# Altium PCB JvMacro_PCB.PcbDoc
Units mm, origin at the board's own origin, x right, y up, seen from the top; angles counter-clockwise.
Board outline 68.58 x 53.34 mm, 2 copper layers (Top Layer, Bottom Layer); 16 components, 30 nets, 104 pads, 8 vias.
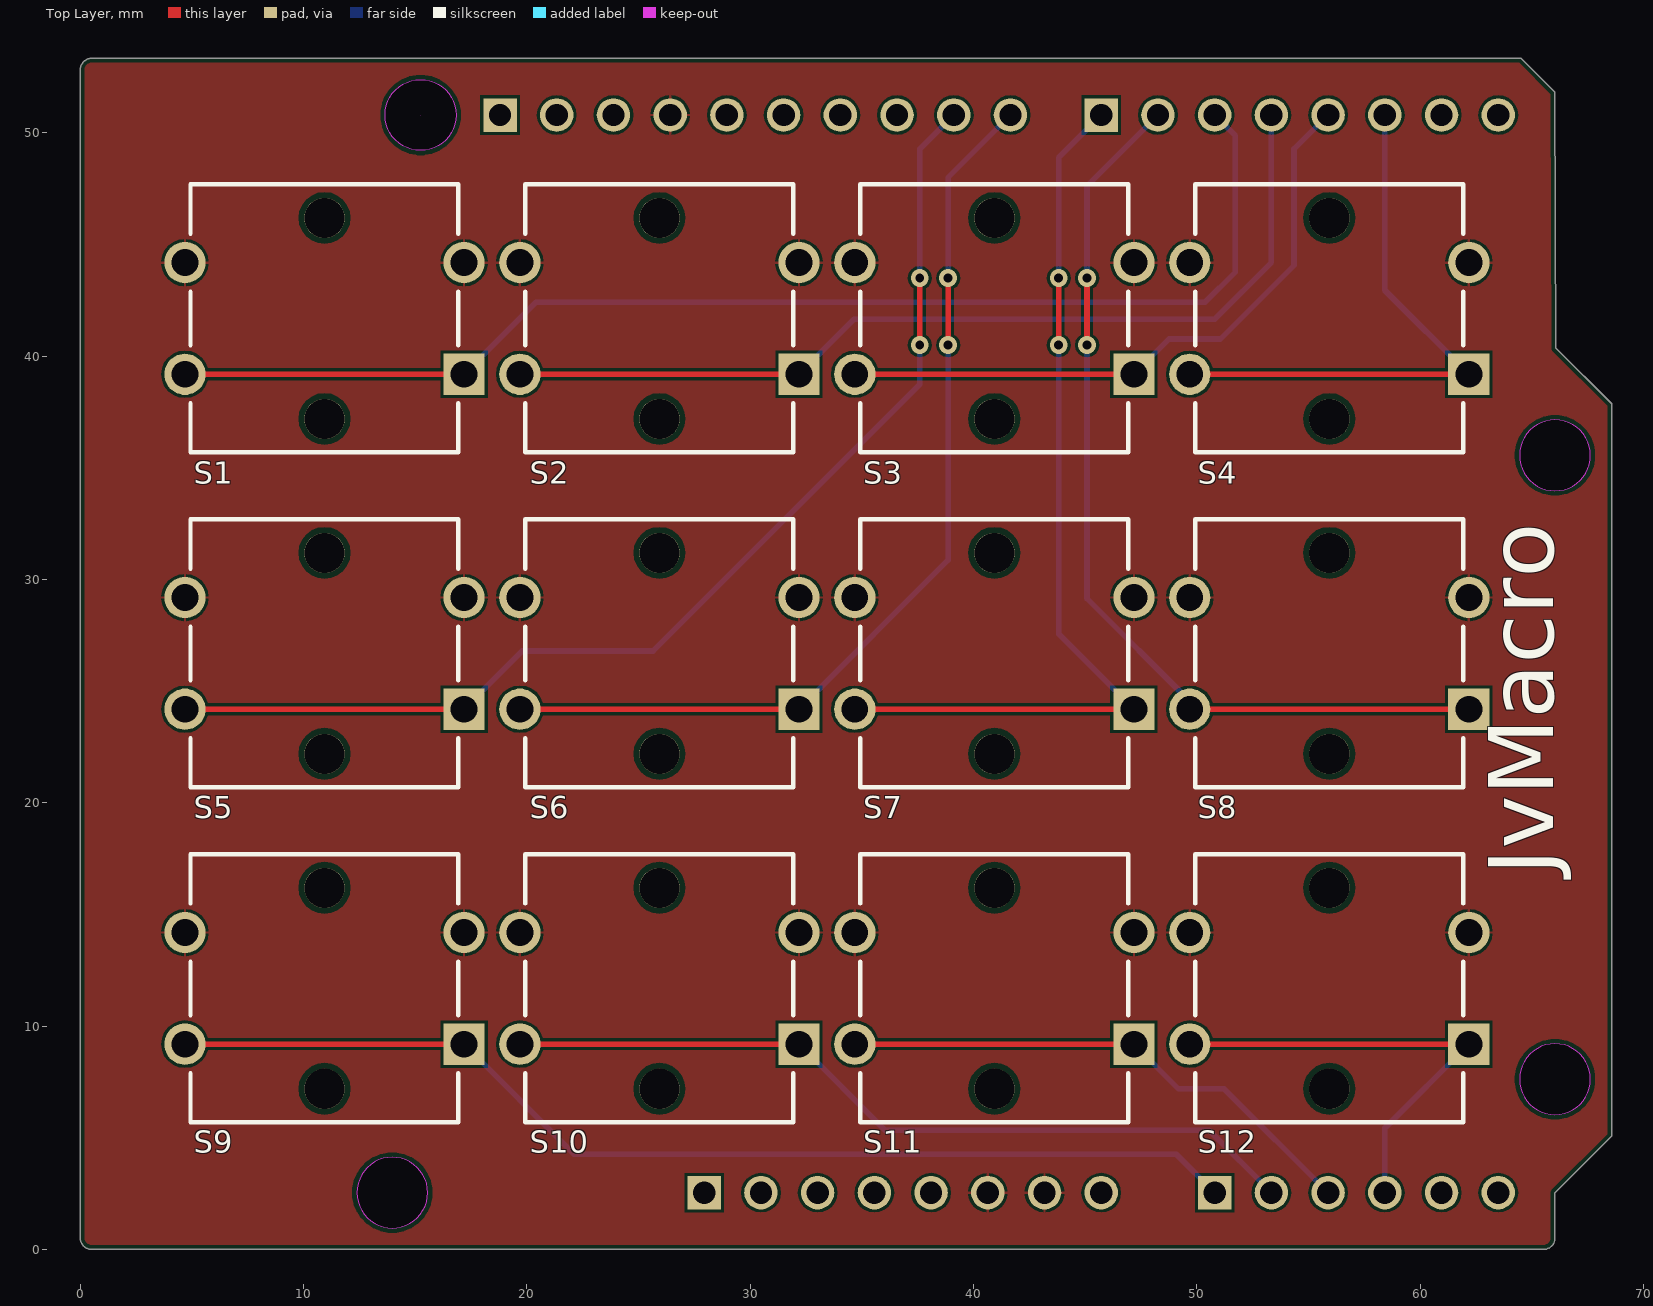
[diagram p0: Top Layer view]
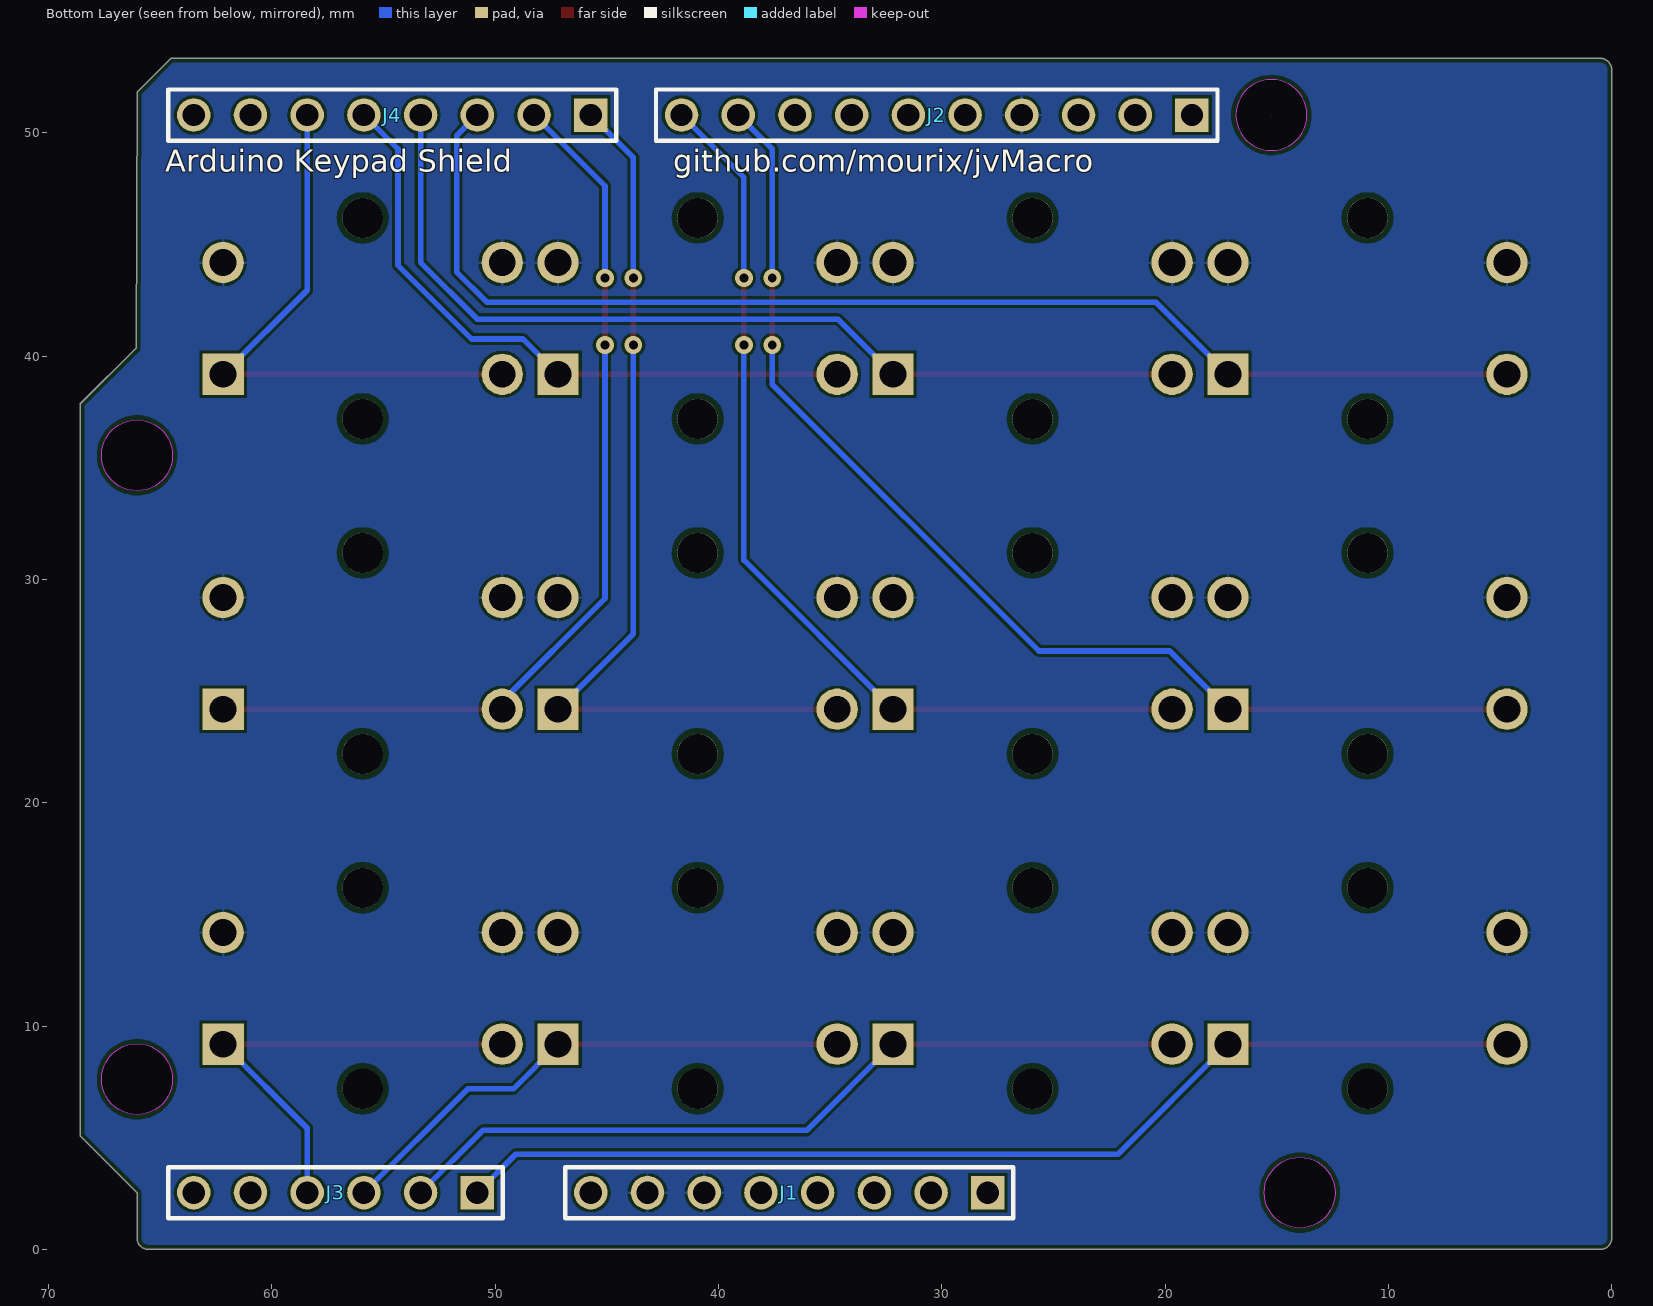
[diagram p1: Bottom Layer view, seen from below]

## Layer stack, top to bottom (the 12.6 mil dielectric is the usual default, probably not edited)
Top Solder: solder mask 0.0102, Solder Resist, Dk 3.5
Top Layer: signal copper 0.0356
Dielectric 1: dielectric 0.32, FR-4, Dk 4.8
Bottom Layer: signal copper 0.0356
Bottom Solder: solder mask 0.0102, Solder Resist, Dk 3.5

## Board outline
0,0.508 0,52.832 cw(c0.508,52.832) 0.508,53.34 64.516,53.34 66.04,51.816 66.07,40.386 66.07,40.376 68.58,37.866 68.58,5.08 66.04,2.54 66.04,0.508 cw(c65.532,0.508) 65.532,0 0.508,0 cw(c0.508,0.508)
cut-out: 15.24,49.212 cw(c15.24,50.8) 13.652,50.8 cw(c15.24,50.8) 15.24,52.387 cw(c15.24,50.8) 16.828,50.8 cw(c15.24,50.8)
cut-out: 64.453,7.62 ccw(c66.04,7.62) 66.04,6.032 ccw(c66.04,7.62) 67.627,7.62 ccw(c66.04,7.62) 66.04,9.207 ccw(c66.04,7.62)
cut-out: 64.453,35.56 ccw(c66.04,35.56) 66.04,33.972 ccw(c66.04,35.56) 67.627,35.56 ccw(c66.04,35.56) 66.04,37.148 ccw(c66.04,35.56)
cut-out: 12.383,2.54 ccw(c13.97,2.54) 13.97,0.953 ccw(c13.97,2.54) 15.557,2.54 ccw(c13.97,2.54) 13.97,4.127 ccw(c13.97,2.54)
cut-out: 15.24,50.8

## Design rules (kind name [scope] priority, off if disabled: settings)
BoardOutlineClearance [All] p1: gap=0.2 ignorepadtopadclearanceinfootprint=FALSE
Clearance [All] p1: gap=0.127 ignorepadtopadclearanceinfootprint=FALSE except(0.25: Arc-Hole Track-Hole SMDPad-Hole THPad-Hole Via-Hole Fill-Hole Poly-Hole Region-Hole Text-Hole)
ComponentClearance [All] p1: gap=0.127 collisioncheckmode=3 verticalgap=0.127 showdistances=TRUE
DiffPairsRouting [All] p1: maxlimit=0.254 minlimit=0.127 mostfreqgap=0.127 toplayer_minwidth=0.127 toplayer_maxwidth=25.4 toplayer_prefwidth=0.127 bottomlayer_minwidth=0.127 bottomlayer_maxwidth=25.4 bottomlayer_prefwidth=0.127 maxuncoupledlength=12.7
Height [All] p1: minheight=0 maxheight=1816.048 prefheight=12.7
HoleSize [All] p1: absolutevalues=TRUE maxlimit=6.3 minlimit=0.3 maxpercent=80.000 minpercent=20.000
HoleToHoleClearance [All] p1: gap=0.25 allowstackedmicrovias=FALSE
MinimumAnnularRing [All] p1: minimumring=0.076
MinimumSolderMaskSliver [All] p1: minsoldermaskwidth=0
PlaneClearance [All] p1: clearance=0.127
PlaneConnect PlaneConnectPowerPads [InPadClass('PowerPads')] p1: planeconnectstyle=Direct reliefexpansion=0.508 reliefentries=4 reliefconductorwidth=0.254 reliefairgap=0.254
PlaneConnect [All] p2: pad.planeconnectstyle=Relief pad.reliefexpansion=0.3 pad.reliefentries=4 pad.reliefconductorwidth=0.127 pad.reliefairgap=0.127 via.planeconnectstyle=Direct via.reliefexpansion=0.3 via.reliefentries=4 via.reliefconductorwidth=0.127 via.reliefairgap=0.127
PolygonConnect PolygonConnectPowerPads [All vs (InPadClass('PowerPads'))] p1: connectstyle=Direct reliefconductorwidth=0.254 reliefentries=4 polygonreliefangle="90 Angle" airgapwidth=0.254
PolygonConnect [All] p2: thpad.connectstyle=Relief thpad.reliefconductorwidth=0.127 thpad.reliefentries=4 thpad.polygonreliefangle="90 Angle" thpad.airgapwidth=0.127 smdpad.connectstyle=Relief smdpad.reliefconductorwidth=0.127 smdpad.reliefentries=4 smdpad.polygonreliefangle="90 Angle" smdpad.airgapwidth=0.127 via.connectstyle=Direct via.reliefconductorwidth=0.127 via.reliefentries=4 via.polygonreliefangle="90 Angle" via.airgapwidth=0.127
RoutingVias [All] p1: holewidth=0.3 width=0.6 viastyle="Through Hole" minholewidth=0.3 minwidth=0.6 maxholewidth=0.6 maxwidth=6.6
SilkToSilkClearance [All] p1: silktosilkclearance=0
SilkToSolderMaskClearance [IsPad] p1: minsilkscreentomaskgap=0.127 clearancetoexposedcopper=TRUE
SolderMaskExpansion [All] p1: expansion=0.075
Width [All] p1: maxlimit=25.4 minlimit=0.127 preferedwidth=0.127 minimp=50.000000 maximp=50.000000 favimp=50.000000
20 further rules are at their usual default settings.

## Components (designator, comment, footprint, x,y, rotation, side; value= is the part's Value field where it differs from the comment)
J1 "Header 8" HDR1X8 27.94,2.54 r0 bottom locked
J2 "Header 10" HDR1X10 18.796,50.8 r0 bottom locked
J3 "Header 6" HDR1X6 50.8,2.54 r0 bottom locked
J4 "Header 8" HDR1X8 45.72,50.8 r0 bottom locked
S1 "B3F" Omron_B3F-4055 10.935,41.69 r0 top
S2 "B3F" Omron_B3F-4055 25.935,41.69 r0 top
S3 "B3F" Omron_B3F-4055 40.935,41.69 r0 top
S4 "B3F" Omron_B3F-4055 55.935,41.69 r0 top
S5 "B3F" Omron_B3F-4055 10.935,26.69 r0 top
S6 "B3F" Omron_B3F-4055 25.935,26.69 r0 top
S7 "B3F" Omron_B3F-4055 40.935,26.69 r0 top
S8 "B3F" Omron_B3F-4055 55.935,26.69 r0 top
S9 "B3F" Omron_B3F-4055 10.935,11.69 r0 top
S10 "B3F" Omron_B3F-4055 25.935,11.69 r0 top
S11 "B3F" Omron_B3F-4055 40.935,11.69 r0 top
S12 "B3F" Omron_B3F-4055 55.935,11.69 r0 top

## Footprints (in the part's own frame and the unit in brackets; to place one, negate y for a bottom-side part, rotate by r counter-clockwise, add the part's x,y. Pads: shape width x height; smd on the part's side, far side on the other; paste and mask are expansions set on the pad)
HDR1X6 [mm] "Connector; Header; 6 Position; Vertical"
  rect 1.5x1.5 hole 1: 1(0,0)
  round 1.5 hole 1: 2(2.54,0) 3(5.08,0) 4(7.62,0) 5(10.16,0) 6(12.7,0)
  silkscreen extent -1.14,-1.14 13.84,1.14, body extent -1.27,-1.27 13.97,1.27, height 6.54
HDR1X8 [mm] "Connector; Header; 8 Position; Vertical"
  rect 1.5x1.5 hole 1: 1(0,0)
  round 1.5 hole 1: 2(2.54,0) 3(5.08,0) 4(7.62,0) 5(10.16,0) 6(12.7,0) 7(15.24,0) 8(17.78,0)
  silkscreen extent -1.14,-1.14 18.92,1.14, body extent -1.27,-1.27 19.05,1.27, height 6.54
HDR1X10 [mm] "Connector; Header; 10 Position; Vertical"
  rect 1.5x1.5 hole 1: 1(0,0)
  round 1.5 hole 1: 2(2.54,0) 3(5.08,0) 4(7.62,0) 5(10.16,0) 6(12.7,0) 7(15.24,0) 8(17.78,0) 9(20.32,0) 10(22.86,0)
  silkscreen extent -1.14,-1.14 24,1.14, body extent -1.27,-1.27 24.13,1.27, height 6.54
Omron_B3F-4055 [mm]
  rect 1.85x1.85 hole 1.2 paste-1000 mask+0: 1(6.25,-2.5)
  round 1.85 hole 1.2 paste-1000 mask+0: 2(-6.25,-2.5) 3(6.25,2.5) 4(-6.25,2.5)
  round 1.8 hole 1.8 unplated paste-1000 mask+0: ""(0,-4.5) ""(0,4.5)
  silkscreen extent -6,-6 6,6, body extent -6.9,-6 6.9,6, height 10.5

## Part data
J1 J4: "2,54mm pitch header, 8 positions"
J2: "2,54mm pitch header, 10 positions"
J3: "2,54mm pitch header, 6 positions"
S1 S2 S3 S4 S5 S6 S7 S8 S9 S10 S11 S12: library part B3F-4055, "B3F pushbutton, 12x12mm, through hole"

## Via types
v1: diameter 0.8, hole 0.4, Top Layer to Bottom Layer, tented both sides, 8 vias

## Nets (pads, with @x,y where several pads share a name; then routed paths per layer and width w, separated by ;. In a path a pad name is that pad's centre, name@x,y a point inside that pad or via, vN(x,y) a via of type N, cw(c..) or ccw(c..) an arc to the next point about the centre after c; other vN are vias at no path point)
3.3V: J1.4
5V: J1.5
A0: J3.1 S9.1 S9.2 | length 48.9
  Top Layer w0.254: S9.2 S9.1
  Bottom Layer w0.254: S9.1 22.113,4.262 49.078,4.262 J3.1
A1: J3.2 S10.1 S10.2 | length 36.4
  Top Layer w0.254: S10.2 S10.1
  Bottom Layer w0.254: S10.1 36.041,5.334 50.546,5.334 J3.2
A2: J3.3 S11.1 S11.2 | length 23.9
  Top Layer w0.254: S11.2 S11.1
  Bottom Layer w0.254: S11.1 49.185,7.19 51.23,7.19 J3.3
A3: J3.4 S12.1 S12.2 | length 20.7
  Top Layer w0.254: S12.2 S12.1
  Bottom Layer w0.254: J3.4 58.42,5.425 S12.1
A4: J3.5
A5: J3.6
ARF: J2.3
D0: J4.8
D1: J4.7
D2: J4.6 S4.1 S4.2 | length 25.7
  Top Layer w0.254: S4.2 S4.1
  Bottom Layer w0.254: J4.6 58.42,42.955 S4.1
D3: J4.5 S3.1 S3.2 | length 29.1
  Top Layer w0.254: S3.2 S3.1
  Bottom Layer w0.254: S3.1 48.762,40.767 51.054,40.767 54.356,44.069 54.356,49.276 J4.5
D4: J4.4 S2.1 S2.2 | length 42.3
  Top Layer w0.254: S2.2 S2.1
  Bottom Layer w0.254: S2.1 34.651,41.656 50.8,41.656 53.34,44.196 J4.4
D5: J4.3 S1.1 S1.2 | length 56.4
  Top Layer w0.254: S1.2 S1.1
  Bottom Layer w0.254: S1.1 20.413,42.418 50.371,42.418 51.726,43.774 51.726,49.874 J4.3
D6: J4.2 S8.1 S8.2 | length 42.4
  Top Layer w0.254: v1@45.085,40.513 v1(45.085,43.5) ; S8.2 S8.1
  Bottom Layer w0.254: v1@45.085,40.513 v1(45.085,40.5) 45.085,29.149 49.685,24.549 S8.2 ; v1@45.085,43.434 v1(45.085,43.5) 45.085,47.625 J4.2
D7: J4.1 S7.1 S7.2 | length 41.4
  Top Layer w0.254: S7.2 S7.1 ; v1@43.815,40.513 v1(43.815,43.5)
  Bottom Layer w0.254: v1@43.815,40.513 v1(43.815,40.5) 43.815,27.56 S7.1 ; v1@43.815,43.434 v1(43.815,43.5) 43.815,48.895 J4.1
D8: J2.10 S6.1 S6.2 | length 43.2
  Top Layer w0.254: S6.2 S6.1 ; v1(38.862,40.5) v1(38.862,43.5)
  Bottom Layer w0.254: S6.1 38.862,30.867 v1(38.862,40.5) v1@38.862,40.64 ; v1(38.862,43.5) 38.862,48.006 J2.10
D9: J2.9 S5.1 S5.2 | length 51.8
  Top Layer w0.254: S5.2 S5.1 ; v1(37.592,40.5) v1(37.592,43.5)
  Bottom Layer w0.254: S5.1 19.792,26.797 25.653,26.797 37.592,38.736 v1(37.592,40.5) v1@37.592,40.64 ; v1(37.592,43.5) 37.592,49.276 J2.9
D10: J2.8
D11: J2.7
D12: J2.6
D13: J2.5
GND: J1.6 J1.7 J2.4 S1.3 S1.4 S2.3 S2.4 S3.3 S3.4 S4.3 S4.4 S5.3 S5.4 S6.3 S6.4 S7.3 S7.4 S8.3 S8.4 S9.3 S9.4 S10.3 S10.4 S11.3 S11.4 S12.3 S12.4
IOR: J1.2
NC: J1.1
RST: J1.3
SCL: J2.1
SDA: J2.2
Vin: J1.8
pads on no net: S1. S2. S3. S4. S5. S6. S7. S8. S9. S10. S11. S12.

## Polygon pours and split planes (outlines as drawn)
GND on Top Layer "GND_L01_P003" (solid, pour order 3): 0,0.508 0,52.832 cw(c0.508,52.832) 0.508,53.34 64.516,53.34 66.04,51.816 66.07,40.386 66.07,40.376 68.58,37.866 68.58,5.08 66.04,2.54 66.04,0.508 cw(c65.532,0.508) 65.532,0 0.508,0 cw(c0.508,0.508)
GND on Bottom Layer "GND_L02_P005" (solid, pour order 5): 0,0.508 0,52.832 cw(c0.508,52.832) 0.508,53.34 64.516,53.34 66.04,51.816 66.07,40.386 66.07,40.376 68.58,37.866 68.58,5.08 66.04,2.54 66.04,0.508 cw(c65.532,0.508) 65.532,0 0.508,0 cw(c0.508,0.508)

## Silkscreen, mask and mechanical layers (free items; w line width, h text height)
Top Overlay:
  text "JvMacro" at 66.929,16.764 h5 r90
Bottom Overlay:
  text "github.com/mourix/jvMacro" at 42.037,48.26 h1
  text "Arduino Keypad Shield" at 64.77,48.26 h1
Mechanical 1:
  circle w0.013: c15.24,50.8 r1.587
  circle w0.013: c66.04,35.56 r1.587
  circle w0.013: c66.04,7.62 r1.587
  circle w0.013: c13.97,2.54 r1.587
  lines w0.1: 0,0.508 ccw(c0.508,0.508) 0.508,0 65.532,0 ccw(c65.532,0.508) 66.04,0.508 66.04,2.54 68.58,5.08 68.58,37.846 68.58,37.866 66.07,40.376 66.07,40.386 66.04,51.816 64.516,53.34 0.508,53.34 ccw(c0.508,52.832) 0,52.832 0,0.508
